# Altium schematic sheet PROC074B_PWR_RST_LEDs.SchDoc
size 431 x 279 mm; Date: Not shown in title block; ApprovedBy: Not shown in title block; CheckedBy: Not shown in title block; Author: Not shown in title block; CompanyName: Not shown in title block; Engineer: Not shown in title block; Organization: Not shown in title block; Address1: Not shown in title block; Address2: Not shown in title block; Address3: Not shown in title block; Address4: Not shown in title block; DocumentNumber: 1; Revision: Use project parameter SCH_Rev; SheetNumber: 4; SheetTotal: 22; PageSetup: Record=PageOptions¦CenterHorizontal=True¦CenterVertical=True¦PrintScale=1.00¦XCorrection=1.00¦YCorrection=1.00¦PrintKind=0¦BorderSize=5000000¦LeftOffset=0¦BottomOffset=0¦Orientation=2¦PaperLength=1000¦PaperWidth=1000¦Scale=100¦PaperSource=15¦PrintQuality=600¦MediaType=1¦DitherType=10¦PaperKind=Letter¦PrintScaleMode=1
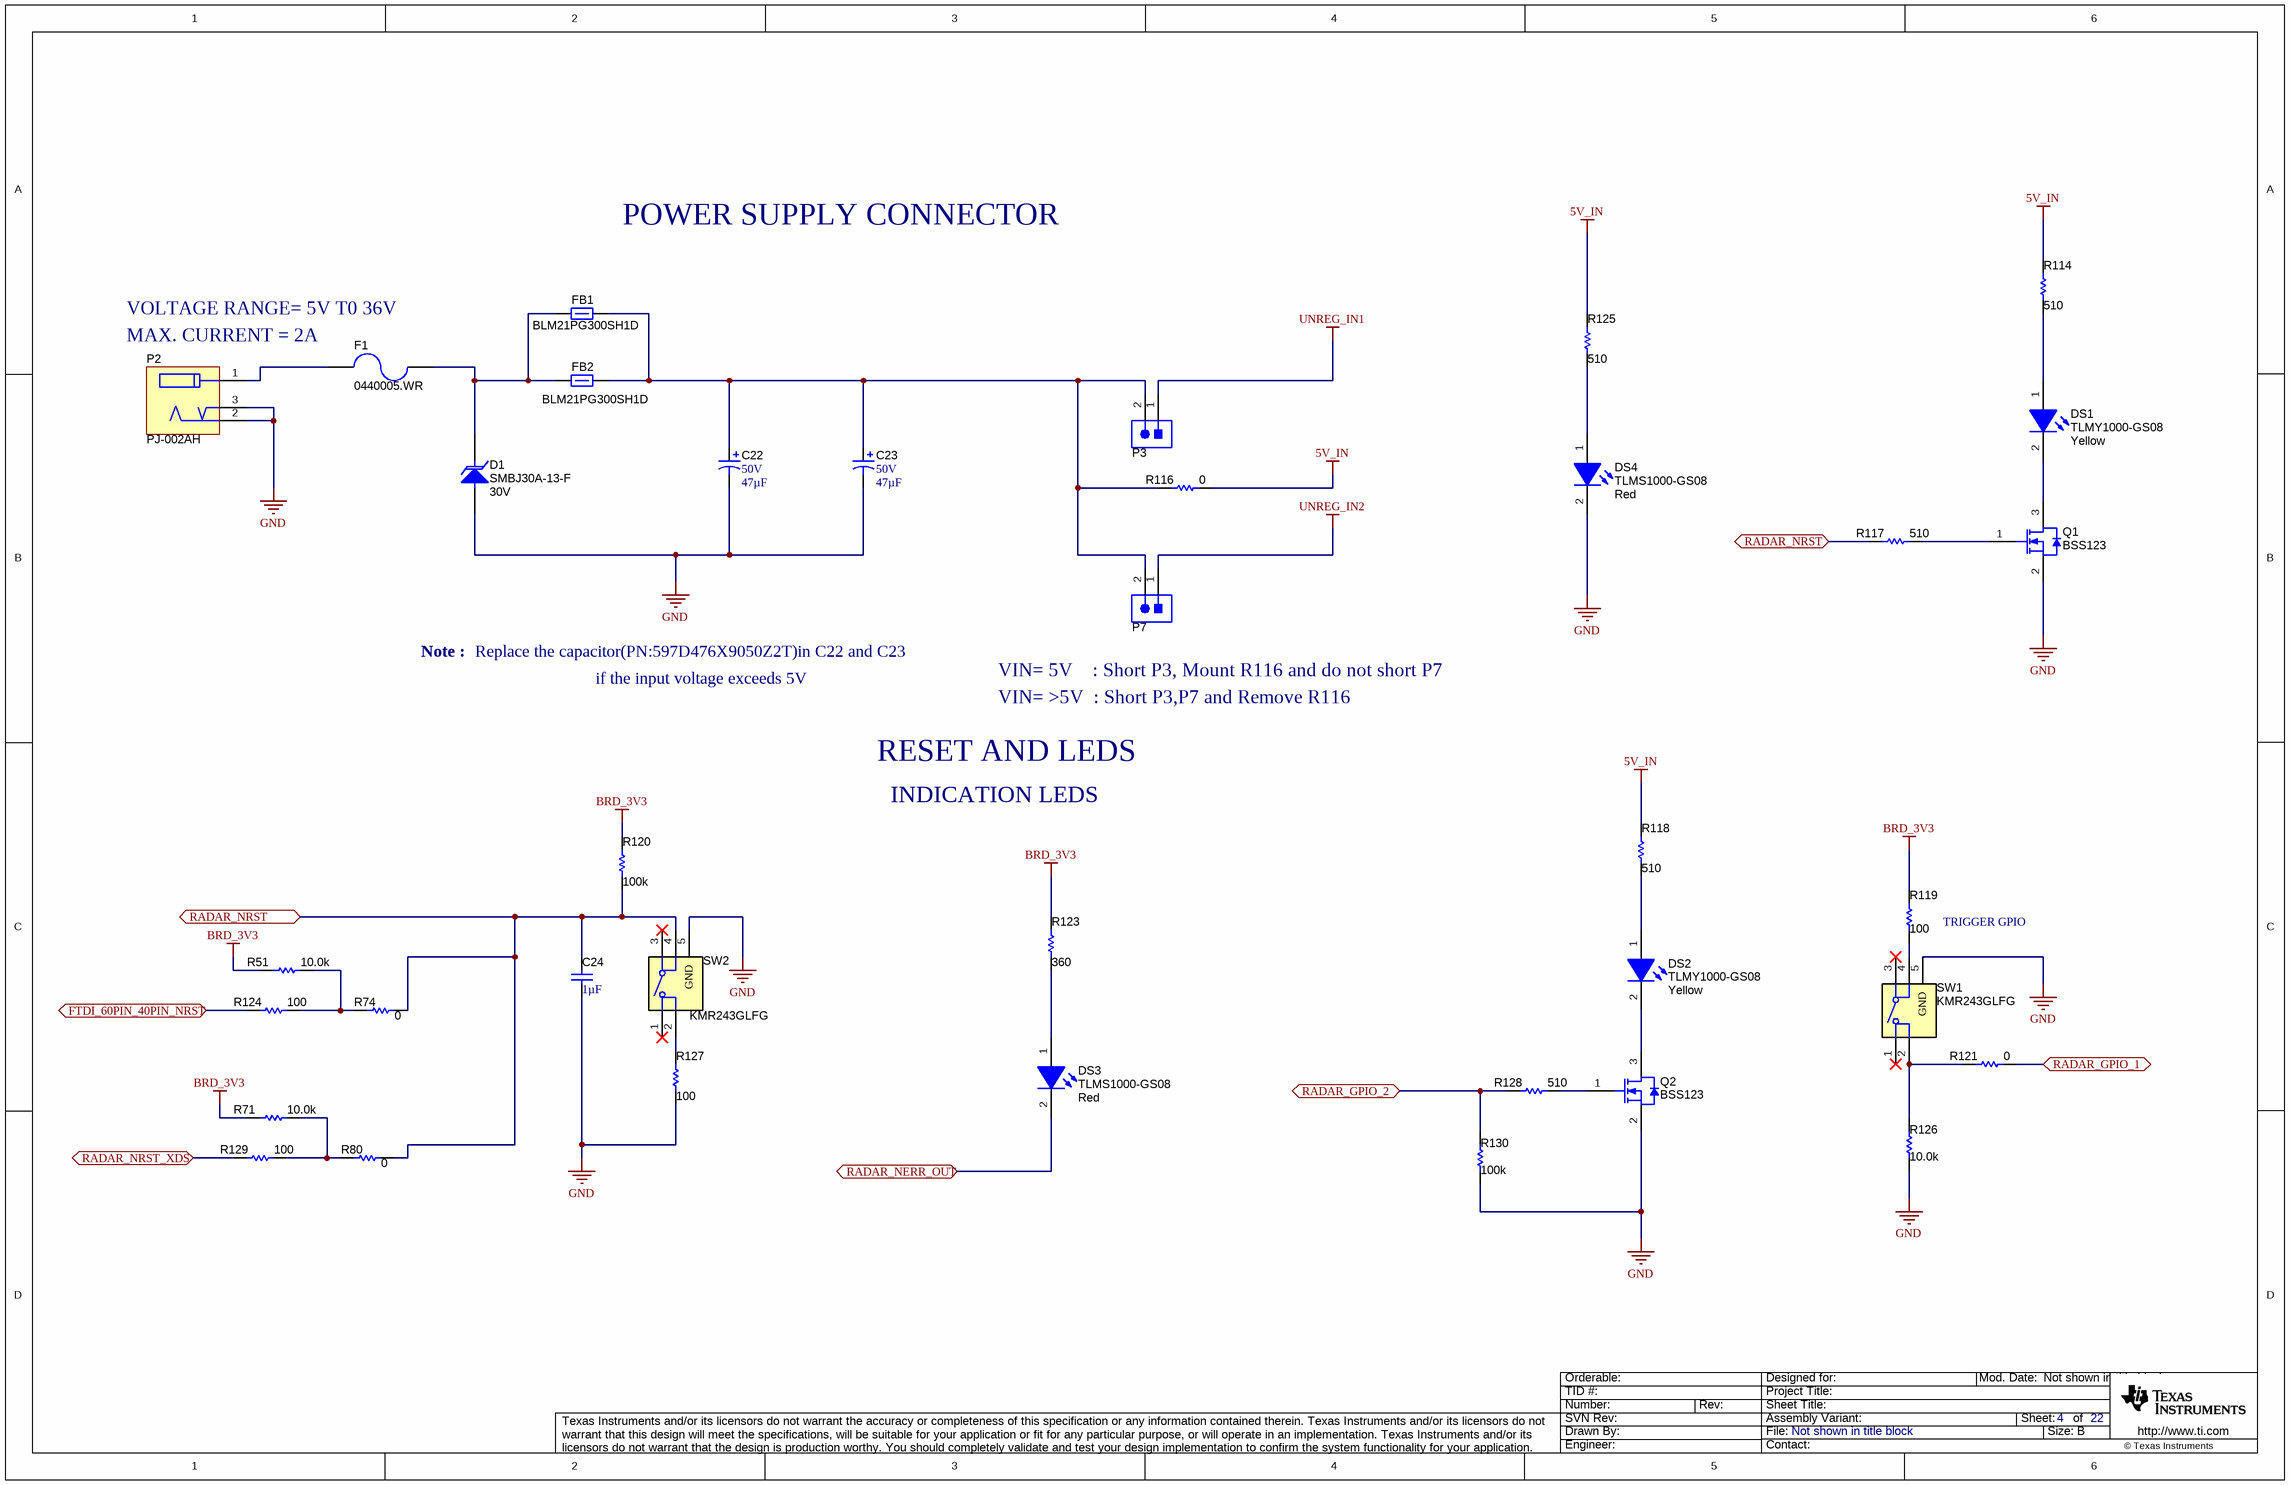
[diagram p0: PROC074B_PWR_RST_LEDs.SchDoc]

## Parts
C22  VDC_V: 50V  ValueDisplayed: 47µF  [597D_Z]  (hidden comment: 597D476X9050Z2T)
C23  VDC_V: 50V  ValueDisplayed: 47µF  [597D_Z]  (hidden comment: 597D476X9050Z2T)
C24  ValueDisplayed: 1µF  [0402L]  (hidden comment: CL05A105KA5NQNC)
D1  SMBJ30A-13-F  value 30V  [SMB]
DS1  TLMY1000-GS08  value Yellow  [TLMx1000_Yellow]
DS2  TLMY1000-GS08  value Yellow  [TLMx1000_Yellow]
DS3  TLMS1000-GS08  value Red  [TLMx1000_Red]
DS4  TLMS1000-GS08  value Red  [TLMx1000_Red]
F1  0440005.WR  [1206]
FB1  BLM21PG300SH1D  [0805_HV]
FB2  BLM21PG300SH1D  [0805_HV]
P2  PJ-002AH  [CUI_PJ-002AH]
P3  TSW-102-07-G-S  [TSW-102-07-X-S]  (value not drawn)
P7  TSW-102-07-G-S  [TSW-102-07-X-S]  (value not drawn)
Q1  BSS123  [SOT-23]
Q2  BSS123  [SOT-23]
R51  ValueDisplayed: 10.0k  [0402L]  (hidden comment: CRCW040210K0FKED)
R71  ValueDisplayed: 10.0k  [0402L]  (hidden comment: CRCW040210K0FKED)
R74  ValueDisplayed: 0  [0402L]  (hidden comment: ERJ-2GE0R00X)
R80  ValueDisplayed: 0  [0402L]  (hidden comment: ERJ-2GE0R00X)
R114  ValueDisplayed: 510  [0402L]  (hidden comment: ERJ-2GEJ511X)
R116  ValueDisplayed: 0  [2010]  (hidden comment: CRCW20100000Z0EF)
R117  ValueDisplayed: 510  [0402L]  (hidden comment: ERJ-2GEJ511X)
R118  ValueDisplayed: 510  [0402L]  (hidden comment: ERJ-2GEJ511X)
R119  ValueDisplayed: 100  [0402L]  (hidden comment: ERJ-2GEJ101X)
R120  ValueDisplayed: 100k  [0402L]  (hidden comment: CRCW0402100KFKED)
R121  ValueDisplayed: 0  [0201_Silk]  (hidden comment: CRCW02010000Z0ED)
R123  ValueDisplayed: 360  [0402L]  (hidden comment: ERJ-2GEJ361X)
R124  ValueDisplayed: 100  [0402L]  (hidden comment: ERJ-2GEJ101X)
R125  ValueDisplayed: 510  [0402L]  (hidden comment: ERJ-2GEJ511X)
R126  ValueDisplayed: 10.0k  [0402L]  (hidden comment: CRCW040210K0FKED)
R127  ValueDisplayed: 100  [0402L]  (hidden comment: ERJ-2GEJ101X)
R128  ValueDisplayed: 510  [0402L]  (hidden comment: ERJ-2GEJ511X)
R129  ValueDisplayed: 100  [0402L]  (hidden comment: ERJ-2GEJ101X)
R130  ValueDisplayed: 100k  [0402L]  (hidden comment: CRCW0402100KFKED)
SW1  KMR243GLFG  [SW_KMR243GLFG]
SW2  KMR243GLFG  [SW_KMR243GLFG]

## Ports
FTDI_60PIN_40PIN_NRST, RADAR_GPIO_1, RADAR_GPIO_2, RADAR_NERR_OUT, RADAR_NRST, RADAR_NRST_XDS

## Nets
5V_IN: R114.2 R116.2 R118.2 R125.2
BRD_3V3: R51.2 R71.2 R119.2 R120.2 R123.2
GND: C22.2(-) C23.2(-) C24.1 D1.2(A) DS4.2(K) P2.2 P2.3 Q1.2(S) Q2.2(S) R126.1 R127.1 R130.1 SW1.5(GND) SW2.5(GND)
UNREG_IN1: P3.1
UNREG_IN2: P7.1
FTDI_60PIN_40PIN_NRST: R124.1 ; port FTDI_60PIN_40PIN_NRST
RADAR_GPIO_1: R121.2 ; port RADAR_GPIO_1
RADAR_GPIO_2: R128.1 R130.2 ; port RADAR_GPIO_2
RADAR_NERR_OUT: DS3.2(K) ; port RADAR_NERR_OUT
RADAR_NRST: C24.2 R74.1 R80.1 R117.1 R120.1 SW2.4 ; port RADAR_NRST
RADAR_NRST_XDS: R129.1 ; port RADAR_NRST_XDS
NetC22_1: C22.1(+) C23.1(+) FB1.2 FB2.2 P3.2 P7.2 R116.1
NetD1_1: D1.1(K) F1.1 FB1.1 FB2.1
NetDS1_1: DS1.1(A) R114.1
NetDS1_2: DS1.2(K) Q1.3(D)
NetDS2_1: DS2.1(A) R118.1
NetDS2_2: DS2.2(K) Q2.3(D)
NetDS3_1: DS3.1(A) R123.1
NetDS4_1: DS4.1(A) R125.1
NetF1_2: F1.2 P2.1
NetQ1_1: Q1.1(G) R117.2
NetQ2_1: Q2.1(G) R128.2
NetR51_1: R51.1 R74.2 R124.2
NetR71_1: R71.1 R80.2 R129.2
NetR119_1: R119.1 SW1.4
NetR121_1: R121.1 R126.2 SW1.2
NetR127_2: R127.2 SW2.2

Not connected (* = marked no-connect by the designer): SW1 1* 3*; SW2 1* 3*

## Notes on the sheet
- POWER SUPPLY CONNECTOR
- VOLTAGE RANGE= 5V T0 36V
- (near P2) MAX. CURRENT = 2A
- Note :
- Replace the capacitor(PN:597D476X9050Z2T)in C22 and C23
- if the input voltage exceeds 5V
- VIN= >5V  : Short P3,P7 and Remove R116
- VIN= 5V    : Short P3, Mount R116 and do not short P7
- RESET AND LEDS
- INDICATION LEDS
- (near R119) TRIGGER GPIO

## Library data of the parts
C22 C23 = CMP-0082253-1: CAP, TA, 47 µF, 50 V, +/- 10%, 0.24 ohm, SMD; Manufacturer: Vishay-Sprague; IRMS_A: 1.1A; SizeAreaWB_mm2: 76.8; SizeArea_mm2: 45.6; AEC Qualified: N; AEC Category: Q200; Value: 47uF; TaMax_C: 125°C; SizeZ_mm: 6.4; Polarized: Y; TaMin_C: -55°C; SizeY_mm: 6; CompType: Capacitor; SizeX_mm: 7.6; ESR_ohm: 2.4d; Cap_Case: 7.6x6x6.4mm
C24 = CMP-0085848-1: CAP, CERM, 1 µF, 25 V,+/- 10%, X5R, 0402; Manufacturer: Samsung Electro-Mechanics; SizeZ_mm: 0.6; AEC Category: Q200; Value: 1uF; SizeArea_mm2: 0.5; TaMax_C: 85°C; TaMin_C: -55°C; SizeX_mm: 1; Cap_Case: 0402; AEC Qualified: N; U/M: EA; Value2: 25V; CompType: Capacitor; SizeAreaWB_mm2: 3
D1 = CMP-0005561-2: Diode, TVS, Uni, 30 V, 48.4 Vc, SMB; Manufacturer: Diodes Inc.; Power_W: 5W; SizeAreaWB_mm2: 44.156; U/M: EA; SizeZ_mm: 2.6; SizeX_mm: 5.6; SizeY_mm: 3.81; SizeArea_mm2: 21.336; AEC Category: Q101
DS1 DS2 = CMP-0078196-1: LED, Yellow, SMD; Manufacturer: Vishay-Semiconductor; Tjmax_C: 120°C; SizeAreaWB_mm2: 4.68; Vr_V: 6V; Power_TotalModule: 40mW; Angle: 160; SizeArea_mm2: 1.28; Ir_A: 10µA; SizeZ_mm: 0.65; Io_A: 2mA; Vf_V: 1.8V; SizeY_mm: 0.8; U/M: EA; Value1: .04W; SizeX_mm: 1.6; Type: AlInGaP
DS3 DS4 = CMP-0078197-1: LED, Red, SMD; Manufacturer: Vishay-Semiconductor; Tjmax_C: 120°C; SizeAreaWB_mm2: 4.68; Vr_V: 6V; Power_TotalModule: 40mW; Angle: 160; SizeArea_mm2: 1.28; Ir_A: 10µA; SizeZ_mm: 0.65; Io_A: 2mA; Vf_V: 1.8V; SizeY_mm: 0.8; U/M: EA; Value1: .04W; SizeX_mm: 1.6; Type: AlInGaP
F1 = CMP-0003458-1: Fuse, 5 A, 32VAC/VDC, SMD; Manufacturer: Littelfuse; Irating_A: 5A; SizeAreaWB_mm2: 10.92; Interrupt_AC: 50A; VAC_V: 32V; SizeZ_mm: 1.35; SizeX_mm: 3.2; SizeY_mm: 1.6; SizeArea_mm2: 5.12; Rtyp_Ohm: 0.012; MeltingTyp: 4.761
FB1 = CMP-0003364-1: Ferrite Bead, 30 ohm @ 100 MHz, 4 A, 0805; Manufacturer: MuRata; ZTyp@100MHz_Ohm: 30; SizeAreaWB_mm2: 6.75; DCR_ohm: 0.014; Value1: 0.014 ohm; Value: 30 ohm; Imax_A: 4A; SizeZ_mm: 1.45; SizeX_mm: 2; SizeY_mm: 1.25; SizeArea_mm2: 2.5; INSTALLATION: DNP
FB2 = CMP-0003364-1: Ferrite Bead, 30 ohm @ 100 MHz, 4 A, 0805; Manufacturer: MuRata; ZTyp@100MHz_Ohm: 30; SizeAreaWB_mm2: 6.75; DCR_ohm: 0.014; Value1: 0.014 ohm; Value: 30 ohm; Imax_A: 4A; SizeZ_mm: 1.45; SizeX_mm: 2; SizeY_mm: 1.25; SizeArea_mm2: 2.5
P2 = CMP-0078270-1: DC POWER JACK, R/A, TH; Manufacturer: CUI Inc.; Gender: Female; Cert_UL: Y; Current_A: 5A; Voltage_V: 24V; Green_REACh: Incomplete; Green_Lifecycle: Not Set
P3 P7 = CMP-0075405-1: Header, 100mil, 2x1, Gold, TH; Manufacturer: Samtec; Pitch_mm: 2.54; Cert_VDE: N; Gender: Male; Cert_CSA: Y; Voltage_V: 550V; Green_REACh: Passed; Current_A: 6.3A; CT: False; Green_Lifecycle: Active; Row_Count: 1; CNHeader: True
Q1 Q2 = CMP-0000947-2: MOSFET, N-CH, 100 V, 0.17 A, SOT-23; Alternate Manufacturer: None; Manufacturer: Fairchild Semiconductor; SizeZ_mm: 1.1; ChType: N; Value2: 1.8 nC; Value1: 1; VdsMax_V: 100V; SizeX_mm: 2.5; SizeY_mm: 3; Vgs_V: 20V; Value: 100V; Rdson45_ohm: 10; SizeArea_mm2: 7.5; AEC Category: Q101; IdsMax_A: 1.7dA; SizeAreaWB_mm2: 14; U/M: EA; QgTyp_nC: 1.8
R51 R71 R126 = CMP-0025958-2: RES, 10.0 k, 1%, 0.063 W, 0402; Manufacturer: Vishay-Dale; Power_W: 63mW; TempCo: 100 ppm/C; Value_Code: 10k0; U/M: EA; Value: 10.0k; EIA_Code: E96; Res_ohm: 10k; SizeX_mm: 1; SizeY_mm: 0.5; SizeZ_mm: 0.6; Value2: 0.063W; VDC_V: 50V; AEC Category: Q200
R74 R80 = CMP-0026992-2: RES, 0, 5%, 0.063 W, 0402; Manufacturer: Panasonic; Power_W: 63mW; TempCo: 600 ppm/C; Value_Code: 0000; U/M: EA; Value: 0; EIA_Code: E24; SizeX_mm: 1; SizeY_mm: 0.5; SizeZ_mm: 0.6; Value2: 0.063W; VDC_V: 50V; AEC Category: Q200
R114 R117 R118 R125 R128 = CMP-0078212-1: RES, 510, 5%, 0.1 W, AEC-Q200 Grade 0, 0402; Manufacturer: Panasonic; Value_Code: 510R; SizeArea_mm2: 0.5; AEC Qualified: Y; AEC Category: Q200; Value: 510; SizeZ_mm: 0.6; EIA_Code: E24; TempCo: 200 ppm/C; AEC Grade: 0; Power_W: 100mW; VDC_V: 50V; Value2: 0.1W; U/M: EA; SizeX_mm: 1
R116 = CMP-0016044-2: RES, 0, 5%, 0.75 W, AEC-Q200 Grade 0, 2010; Manufacturer: Vishay-Dale; Power_W: 750mW; TempCo: ppm/C; Value_Code: 0000; U/M: EA; Value: 0; EIA_Code: E24; SizeX_mm: 5; SizeY_mm: 2.5; SizeZ_mm: 1.66; Value2: 0.75W; SizeArea_mm2: 12.5; AEC Qualified: Y; AEC Category: Q200
R119 R124 R127 R129 = CMP-0026993-2: RES, 100, 5%, 0.1 W, AEC-Q200 Grade 0, 0402; Manufacturer: Panasonic; Power_W: 100mW; TempCo: 200 ppm/C; Value_Code: 100R; U/M: EA; Value: 100; EIA_Code: E24; SizeX_mm: 1; SizeY_mm: 0.5; SizeZ_mm: 0.6; Value2: 0.1W; AEC Qualified: Y; AEC Grade: 0; AEC Category: Q200
R120 = CMP-0025950-2: RES, 100 k, 1%, 0.063 W, 0402; Manufacturer: Vishay-Dale; Power_W: 63mW; TempCo: 100 ppm/C; U/M: EA; Value: 100k; EIA_Code: E96; SizeX_mm: 1; SizeY_mm: 0.5; SizeZ_mm: 0.6; Value2: 0.063W; CompType: Resistor; VDC_V: 50V; AEC Category: Q200
R121 = CMP-0027008-3: RES, 0, 5%, 0.05 W, 0201; Manufacturer: Vishay-Dale; Power_W: 50mW; TempCo: ppm/C; Value_Code: 0000; U/M: EA; Value: 0; EIA_Code: E24; SizeX_mm: 0.6; SizeY_mm: 0.3; SizeZ_mm: 0.26; Value2: 0.05W; SizeArea_mm2: 0.18; AEC Qualified: N; AEC Category: Q200
R123 = CMP-0078194-1: RES, 360, 5%, 0.1 W, AEC-Q200 Grade 0, 0402; Manufacturer: Panasonic; Value_Code: 360R; SizeArea_mm2: 0.5; AEC Qualified: Y; AEC Category: Q200; Value: 360; SizeZ_mm: 0.6; EIA_Code: E24; TempCo: 200 ppm/C; AEC Grade: 0; Power_W: 100mW; VDC_V: 50V; Value2: 0.1W; U/M: EA; SizeX_mm: 1
R130 = CMP-0025950-2: RES, 100 k, 1%, 0.063 W, 0402; Manufacturer: Vishay-Dale; Power_W: 63mW; TempCo: 100 ppm/C; U/M: EA; Value: 100k; EIA_Code: E96; SizeX_mm: 1; SizeY_mm: 0.5; SizeZ_mm: 0.6; Value2: 0.063W; VDC_V: 50V; AEC Category: Q200
SW1 SW2 = CMP-0002325-1: Switch, SPST-NO, Off-Mom, 0.01 A, 32 VDC, SMD; Manufacturer: C&K Components; CurrentRating_mA: 10A; PositionCount: 1; SizeX_mm: 4.6; SizeY_mm: 2.8; SizeZ_mm: 1.9; SizeArea_mm2: 12.88; VDC_V: 32V; SizeAreaWB_mm2: 21.28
